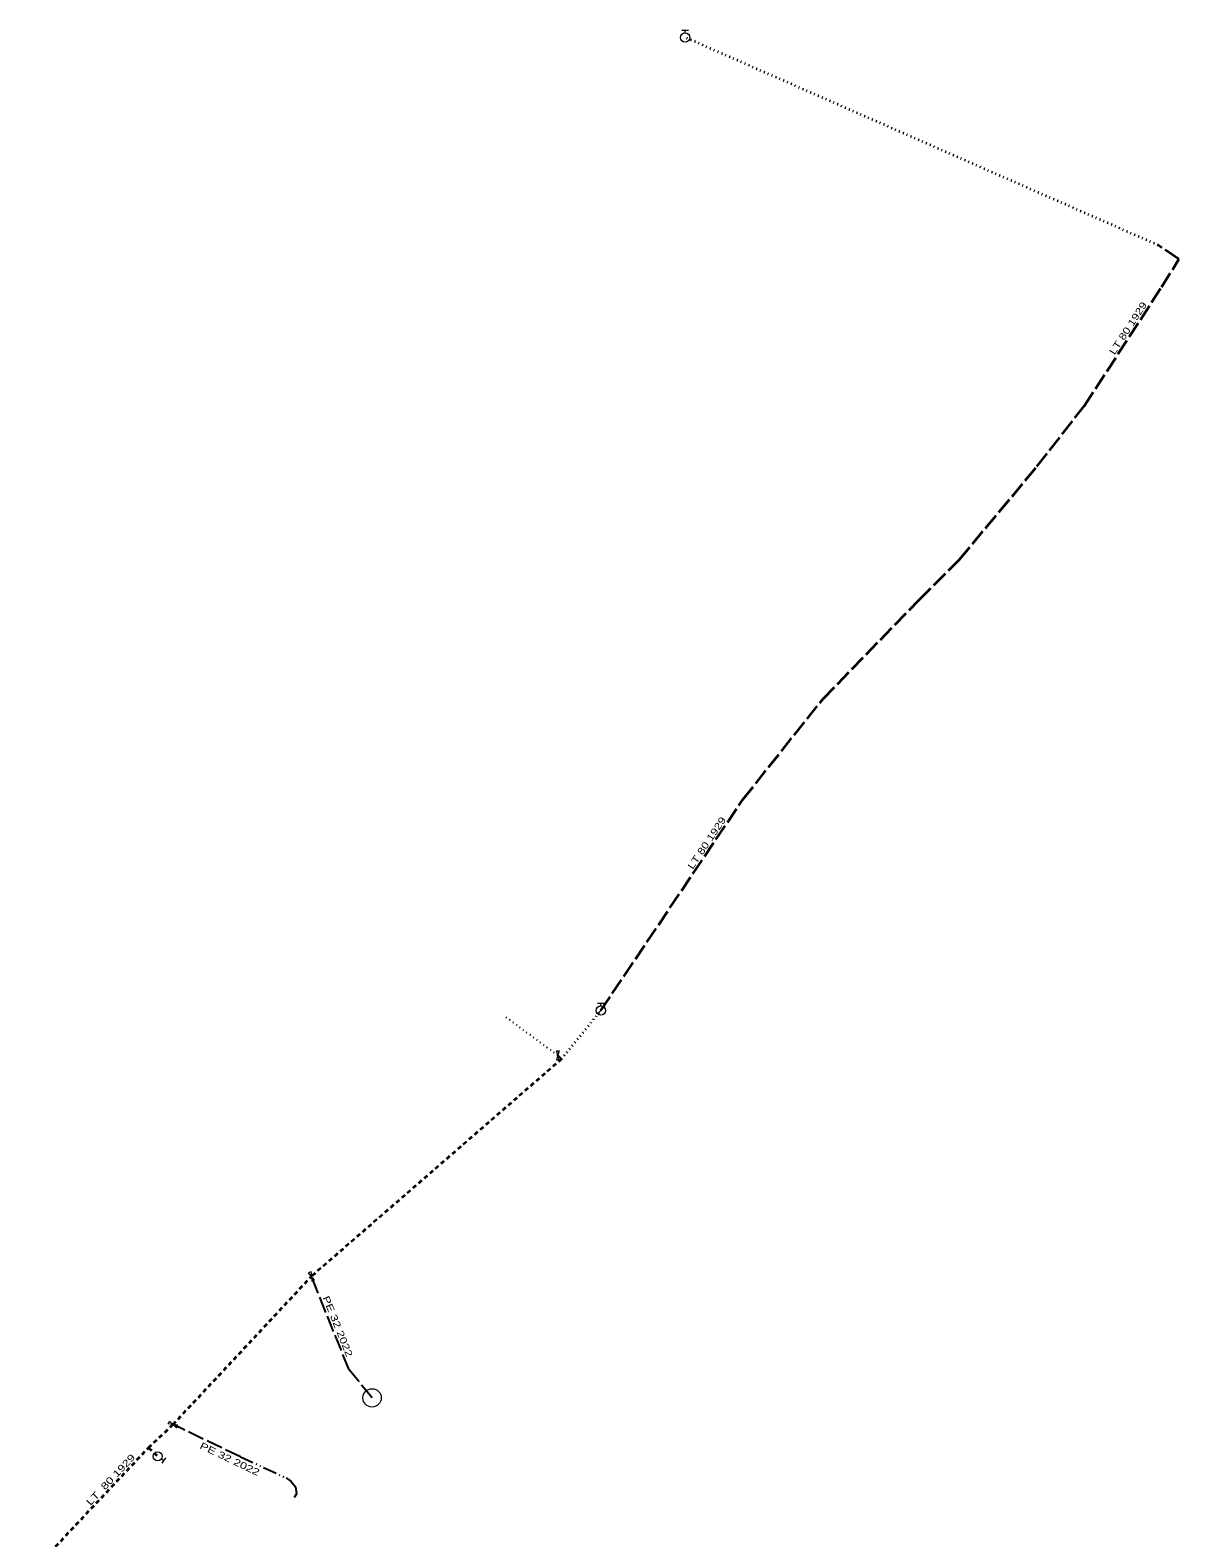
# Model space of a CAD drawing. Extents: x -582626 to -580899, y -1097611 to -1096610.
# Drawn here: x -582004.6 to -581879.2, y -1097403.5 to -1097238.9 of the extents above; entities that cross this region are included whole.
import ezdxf
from ezdxf.enums import TextEntityAlignment as Align

# ---------------------------------------------------------------- set-up
doc = ezdxf.new("R2010")
doc.units = 0
doc.header["$LTSCALE"] = 0.3
for name, pattern in [('DASH_DOUBLE_DOT', [9.2, 5, -1.2, 0.3, -1.2, 0.3, -1.2]), ('DOTTED', [1.5, 0.3, -1.2]), ('LONG_DASHED', [7.5, 6, -1.5]), ('SHORT_DASHED', [2.7, 1.5, -1.2])]:
    doc.linetypes.add(name, pattern=pattern)
for name, color, linetype, lineweight in [('10', 7, 'Continuous', 13), ('35', 7, 'LONG_DASHED', 35), ('36', 7, 'DASH_DOUBLE_DOT', 35), ('50', 7, 'LONG_DASHED', 25), ('51', 7, 'DOTTED', 25)]:
    doc.layers.add(name, color=color, linetype=linetype, lineweight=lineweight)
doc.layers.add('16', color=7, linetype='Continuous')
doc.layers.add('19', color=7, linetype='Continuous')

msp = doc.modelspace()

# ---------------------------------------------------------------- linework, layer by layer
at = {"layer": '10'}
for p, q in [((-581933.461, -1097238.878), (-581932.761, -1097238.878)), ((-581933.111, -1097239.178), (-581933.111, -1097238.878)), ((-581942.674, -1097346.25), (-581941.967, -1097345.543)), ((-581942.67, -1097345.096), (-581941.97, -1097345.096)), ((-581942.32, -1097345.396), (-581942.32, -1097345.096)), ((-581990.295, -1097394.845), (-581990.05, -1097395.018)), ((-581989.848, -1097394.733), (-581990.253, -1097395.304))]:
    msp.add_line(p, q, dxfattribs=at)
for points in [[(-581947.005, -1097350.783), (-581947.155, -1097350.283), (-581946.855, -1097350.283), (-581947.005, -1097350.783), (-581947.155, -1097351.283), (-581946.855, -1097351.283)], [(-581973.913, -1097374.919), (-581974.243, -1097374.514), (-581973.965, -1097374.4), (-581973.913, -1097374.919), (-581973.861, -1097375.438), (-581973.583, -1097375.324)], [(-581989.022, -1097391.087), (-581989.537, -1097391.003), (-581989.406, -1097390.734), (-581989.022, -1097391.087), (-581988.638, -1097391.44), (-581988.507, -1097391.171)]]:
    msp.add_lwpolyline(points, close=True, dxfattribs=at)
for centre, radius in [((-581933.111, -1097239.678), 0.5), ((-581942.3198, -1097345.8957), 0.5), ((-581967.287, -1097388.176), 1), ((-581990.703, -1097394.556), 0.5)]:
    msp.add_circle(centre, radius, dxfattribs=at)
at = {"layer": '35'}
msp.add_lwpolyline([(-581942.32, -1097345.896), (-581926.811, -1097322.87), (-581918.06, -1097311.872), (-581907.55, -1097301.049), (-581903.19, -1097296.688), (-581894.712, -1097286.518), (-581889.543, -1097279.916), (-581881.104, -1097266.94), (-581879.212, -1097263.886), (-581881.455, -1097262.364)], dxfattribs=at)
at = {"layer": '36', "linetype": 'DOTTED'}
for p, q in [((-581881.455, -1097262.364), (-581933.111, -1097239.678)), ((-581946.6, -1097351.185), (-581942.32, -1097345.896))]:
    msp.add_line(p, q, dxfattribs=at)
at = {"layer": '36', "linetype": 'SHORT_DASHED'}
for p, q in [((-581946.6, -1097351.185), (-581973.913, -1097374.919)), ((-582004.619, -1097407.341), (-581991.695, -1097393.622)), ((-581991.695, -1097393.622), (-581990.703, -1097394.556))]:
    msp.add_line(p, q, dxfattribs=at)
msp.add_lwpolyline([(-581991.695, -1097393.622), (-581989.022, -1097391.087), (-581973.913, -1097374.919)], dxfattribs=at)
at = {"layer": '50'}
msp.add_line((-581981.658, -1097394.614), (-581989.022, -1097391.087), dxfattribs=at)
msp.add_lwpolyline([(-581967.287, -1097388.176), (-581969.803, -1097385.107), (-581973.913, -1097374.919)], dxfattribs=at)
at = {"layer": '51'}
msp.add_line((-581952.681, -1097346.609), (-581947.005, -1097350.783), dxfattribs=at)
at = {"layer": '51', "linetype": 'SHORT_DASHED'}
msp.add_line((-581947.005, -1097350.783), (-581946.6, -1097351.185), dxfattribs=at)
at = {"layer": '51', "linetype": 'DASH_DOUBLE_DOT'}
msp.add_lwpolyline([(-581981.658, -1097394.614), (-581976.664, -1097396.925), (-581976.129, -1097397.292), (-581975.65, -1097397.884), (-581975.537, -1097398.645), (-581975.79, -1097399.066)], dxfattribs=at)

# ---------------------------------------------------------------- texts
at = {"layer": '16'}
for s, rotation, width, p in [('LT 80 1929', 56.962, 1.3, (-581884.4413, -1097271.6134)), ('LT 80 1929', 56.038, 1.3, (-581930.4417, -1097327.8115)), ('LT  80 1929', 46.709, 1.35, (-581995.5608, -1097397.3611))]:
    msp.add_text(s, height=0.75, rotation=rotation, dxfattribs=dict(at, width=width)).set_placement(p, align=Align.CENTER)
at = {"layer": '19', "width": 1.35}
for rotation, p in [(291.97, (-581971.387, -1097380.5127)), (334.408, (-581982.988, -1097395.1914))]:
    msp.add_text('PE 32 2022', height=0.75, rotation=rotation, dxfattribs=at).set_placement(p, align=Align.CENTER)

doc.saveas('drawing.dxf')
